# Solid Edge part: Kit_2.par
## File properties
Sűrűség: 0,000 kg/m^3
Pontosság: 0,990
Author: ahadarics
Last saved by: psaghy
Revision: 78
Username: ahadarics
Dokumentum tartalom típus: 0
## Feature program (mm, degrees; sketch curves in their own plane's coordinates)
base feature "unnamed BaseFeature 1"
thread "unnamed Thread 1"
sketch for "unnamed Hole 1" plane through (17.575, -12.675, 4.5) normal (0, 0, -1) x-axis (0.38075, 0.924678, 0)
  hole centre (-3.8102, 0.136) bore radius 2.4585
hole "unnamed Hole 1" through
sketch for "unnamed Hole 2" plane through (17.575, -12.675, 4.5) normal (0, 0, -1) x-axis (0.38075, 0.924678, 0)
  hole centre (26.2418, -12.2384) bore radius 2.4585
hole "unnamed Hole 2" through
sketch for "unnamed Hole 3" plane through (17.575, -12.675, 4.5) normal (0, 0, -1) x-axis (0.38075, 0.924678, 0)
  hole centre (-16.1846, -29.9161) bore radius 2.4585
hole "unnamed Hole 3" through
sketch for "unnamed Hole 4" plane through (17.575, -12.675, 4.5) normal (0, 0, -1) x-axis (0.38075, 0.924678, 0)
  hole centre (13.8675, -42.2904) bore radius 2.4585
hole "unnamed Hole 4" through
pattern "unnamed Pattern 1" of "unnamed Hole 1", "unnamed Hole 2", "unnamed Hole 3", "unnamed Hole 4"
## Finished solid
Body 1: solid body, 293 faces, 721 edges, 450 vertices, 4 internal voids.
  Faces by surface: plane 140, cylinder 68, swept 55, torus 20, cone 9, spline 1
  Edges by curve: line 433, circle 161, spline 122, curve on surface 4, intersection 1
Bounding box of the edges (mm; curved faces can reach further): 49.000 x 49.000 x 14.100, from (-24.5, -24.5, 0) to (24.5, 24.5, 14.1).
Cylindrical faces by radius (mm): R0.2 x30, R0.335 x1, R0.5307 x1, R1.25 x1, R2.4585 x4, R2.5402 x12, R2.6 x4, R3.75 x4, R4 x4, R4.283 x1, R4.5 x5, R10.6633 x1
Conical faces (half-angle, radius in mm at the cone's reference point): 0.5 deg R8 x4, 45 deg R2.8085 x4, 45 deg R4.65 x1
Toroidal faces (ring radius, tube radius in mm): R2.9402 r0.4 x12, R3.55 r0.2 x8
Planar faces by outward normal: +x 12, +y 12, +z 1, -x 10, -y 12, -z 18, oblique 75
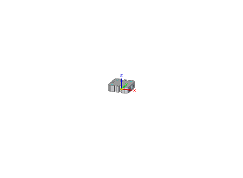
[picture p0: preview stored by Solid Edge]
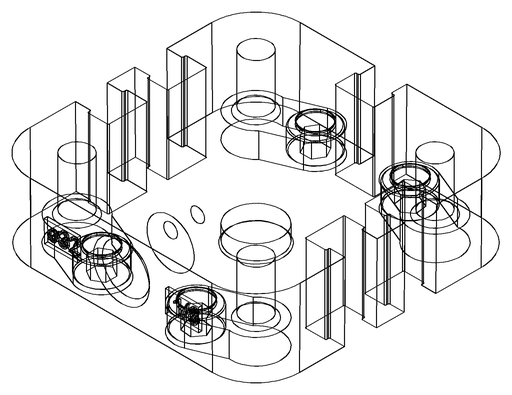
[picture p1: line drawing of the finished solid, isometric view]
